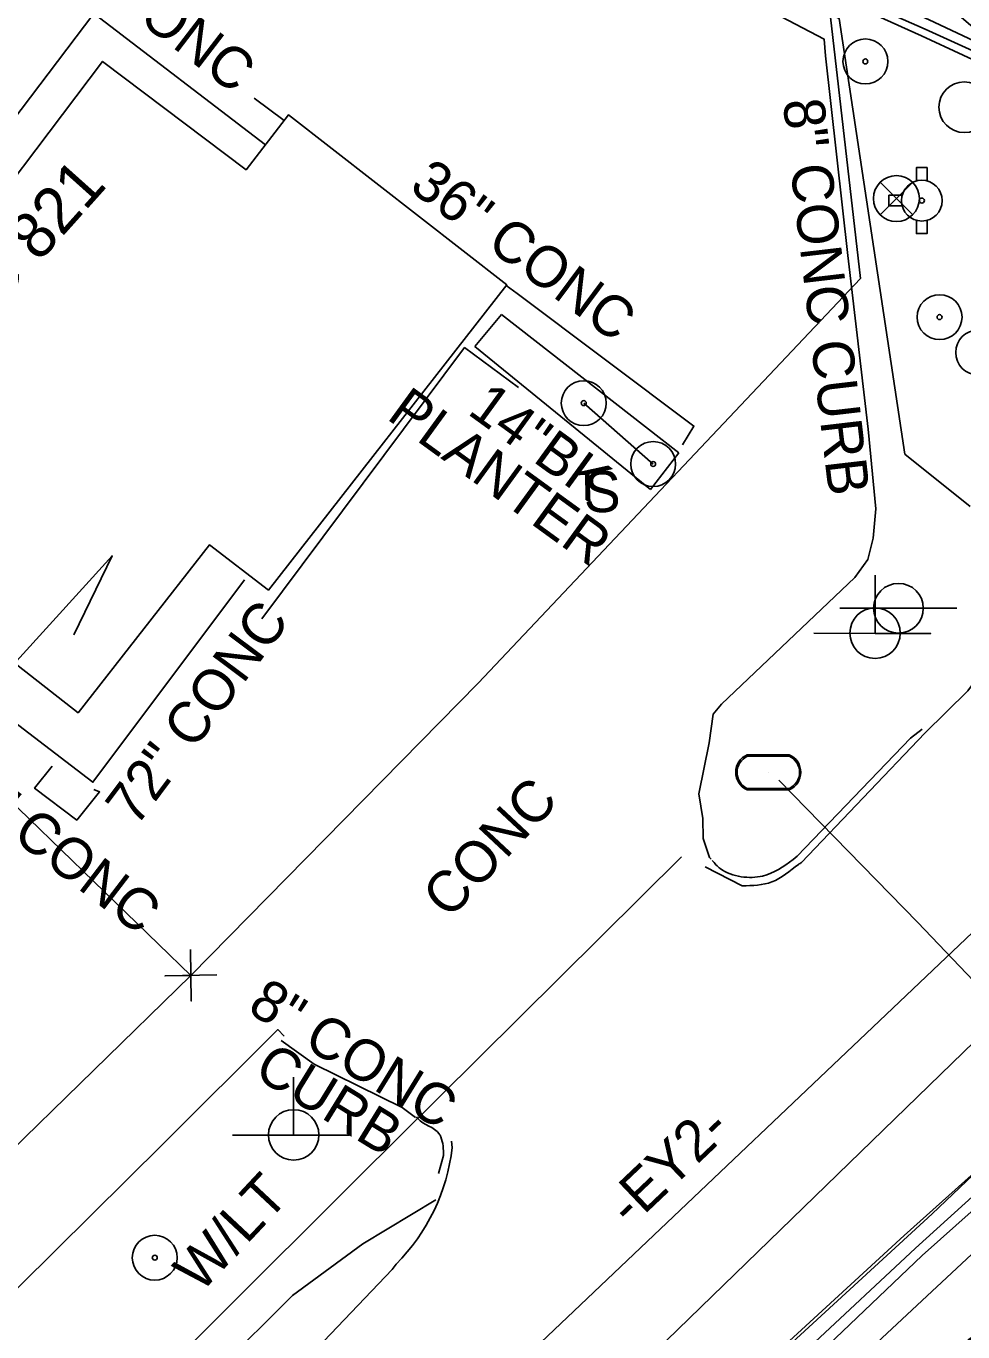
# Model space of a CAD drawing. Extents: x 2089016 to 2094354, y 862840 to 864725.
# Drawn here: x 2091453.6 to 2091544.5, y 863468.2 to 863595 of the extents above; entities that cross this region are included whole.
import ezdxf

# ---------------------------------------------------------------- set-up
doc = ezdxf.new("R2010")
doc.units = 0
for name, color, linetype in [('Exist Building', 7, 'Continuous'), ('Exist Building Text', 7, 'Continuous'), ('Exist Horizontal Alignment', 7, 'Continuous'), ('Exist Other Culture Sign Text', 7, 'Continuous'), ('Exist Property Corner CELL', 7, 'Continuous'), ('Exist Property Deed Book Text', 7, 'Continuous'), ('Exist Property Line', 7, 'Continuous'), ('Exist Property Same Owner Line CELL', 7, 'Continuous'), ('Exist Right of Way Line', 7, 'Continuous'), ('Exist Roads Curbs', 7, 'Continuous'), ('Exist Roads Curbs Text', 7, 'Continuous'), ('Exist Roads EOP', 7, 'Continuous'), ('Exist Roads EOP Other', 7, 'Continuous'), ('Exist Roads EOP Other Text', 7, 'Continuous'), ('Exist Roads EOT', 7, 'Continuous'), ('Exist Roads Soil', 7, 'Continuous'), ('Exist Structure Minor Pipes RCP 18 Inch Text', 7, 'Continuous'), ('Exist Utilities Other Unknown UG SUE LOS B', 7, 'Continuous'), ('Exist Utilities Power Joint Use Telephone Text', 7, 'Continuous'), ('Exist Utilities Telephone UG Cable SUE LOS B', 7, 'Continuous'), ('Exist Utilities Telephone UG FO SUE LOS B', 7, 'Continuous'), ('Exist Utilities Water UG Line SUE LOS B', 7, 'Continuous'), ('Exist Utilities Water UG Line SUE LOS C', 7, 'Continuous'), ('Pattern 1', 7, 'Continuous'), ('Prop Conc Driveway', 7, 'Continuous'), ('Prop Drainage Structure Junction Box Convert From Drop Inlet Label', 7, 'Continuous'), ('Prop Drainage Structure Pipe RCP 30in Class IV Label', 7, 'Continuous'), ('Prop Drainage Structure Pipe RCP 36in Class IV', 7, 'Continuous'), ('Prop Erosion Embankment Toe Protection with Rip Rap 2 Detail CELL', 7, 'Continuous'), ('Prop Erosion Rip Rap Pad at Outlet Label', 7, 'Continuous'), ('Prop SS Fill Line', 7, 'Continuous'), ('R5707_NCDOT_FS_170814 - Exist Property Same Owner Line CELL', 7, 'Continuous'), ('R5707_NCDOT_FS_170814 - Exist Roads EOT', 7, 'Continuous')]:
    doc.layers.add(name, color=color, linetype=linetype)

msp = doc.modelspace()

# ---------------------------------------------------------------- linework, layer by layer
at = {"layer": 'Exist Building'}
for p, q in [((2091497.12, 863563.86), (2091499.7, 863566.97)), ((2091499.7, 863566.97), (2091516.9, 863553.56)), ((2091514.15, 863549.99), (2091497.12, 863563.86)), ((2091516.9, 863553.56), (2091514.15, 863549.99))]:
    msp.add_line(p, q, dxfattribs=at)
msp.add_lwpolyline([(2091430.07, 863550.64), (2091460.98, 863591.55), (2091474.9, 863581.03), (2091479.03, 863586.37), (2091500.2, 863569.85), (2091477.08, 863540.22), (2091471.36, 863544.62), (2091458.6, 863528.31)], close=True, dxfattribs=at)
at = {"layer": 'Exist Horizontal Alignment'}
msp.add_line((2091563.2, 863523.9), (2091414.2, 863382.31), dxfattribs=at)
at = {"layer": 'Exist Property Corner CELL'}
msp.add_line((2091469.55, 863502.82), (2091469.55, 863502.82), dxfattribs=at)
msp.add_lwpolyline([(2091472.05, 863502.86), (2091467.05, 863502.77), (2091469.55, 863502.82), (2091469.59, 863500.32), (2091469.51, 863505.32)], dxfattribs=at)
at = {"layer": 'Exist Property Line'}
msp.add_line((2091397.62, 863572.38), (2091469.55, 863502.82), dxfattribs=at)
at = {"layer": 'Exist Property Same Owner Line CELL'}
msp.add_lwpolyline([(2091432.78, 863514.65), (2091428.25, 863506.53), (2091461.89, 863543.56), (2091458.17, 863535.87)], dxfattribs=at)
at = {"layer": 'Exist Right of Way Line'}
for p, q in [((2091531.4, 863597.96), (2091534.53, 863570.46)), ((2091534.53, 863570.46), (2091497.44, 863531.19)), ((2091497.44, 863531.19), (2091469.55, 863502.82)), ((2091469.55, 863502.82), (2091387.26, 863422.48))]:
    msp.add_line(p, q, dxfattribs=at)
at = {"layer": 'Exist Roads Curbs'}
msp.add_line((2091494.06, 863485.32), (2091493.58, 863483.58), dxfattribs=at)
for points in [[(2091506.04, 863606.89), (2091507.45, 863606.08), (2091531.01, 863593.71), (2091531.16, 863592.1), (2091533.32, 863572.69), (2091535.29, 863555.85), (2091536.04, 863548.12), (2091535.77, 863545.25), (2091535.25, 863543.2), (2091534, 863541.43), (2091521.05, 863529.14), (2091520.24, 863528.16), (2091519.85, 863525.4), (2091518.85, 863520.45), (2091519.25, 863518.04), (2091519.28, 863516.11), (2091519.9, 863514.25), (2091520.06, 863514.09)], [(2091476.78, 863583.45), (2091460.14, 863596.2), (2091444.26, 863575.3), (2091424.36, 863548.86), (2091460.04, 863521.56), (2091474.74, 863541.21)], [(2091478.6, 863585.81), (2091475.68, 863587.99)], [(2091517.26, 863554.31), (2091518.37, 863556.14), (2091501.22, 863569.01), (2091500.16, 863569.8)], [(2091476.43, 863537.44), (2091496.12, 863563.77), (2091501.36, 863559.9)], [(2091528.02, 863514.06), (2091528.41, 863514.38), (2091539.41, 863525.84), (2091540.53, 863526.71)], [(2091491.36, 863489.01), (2091490.07, 863489.98), (2091481.51, 863494.2), (2091478.31, 863496.51)]]:
    msp.add_lwpolyline(points, dxfattribs=at)
for points in [[(2091520.14, 863513.98), (2091520.93, 863513.18), (2091522.97, 863512.4), (2091525.04, 863512.46), (2091528.02, 863514.06)], [(2091491.46, 863489.07), (2091491.58, 863488.91), (2091493.65, 863487.44), (2091493.81, 863487.14), (2091494.06, 863485.32)]]:
    msp.add_spline(points, degree=3, dxfattribs=at)
at = {"layer": 'Exist Roads EOP'}
for p, q in [((2091523.07, 863511.51), (2091519.47, 863513.36)), ((2091494.84, 863486.71), (2091494.92, 863486.11))]:
    msp.add_line(p, q, dxfattribs=at)
for points in [[(2091614.68, 863551.59), (2091577.53, 863513.94), (2091541.5, 863479.68), (2091509.96, 863450.67), (2091494.8, 863436.99), (2091459.99, 863406.66), (2091416.33, 863367.37), (2091398.26, 863350.73), (2091360.43, 863313.58), (2091358.8, 863312), (2091365.83, 863304.95)], [(2091552.39, 863540.36), (2091544.96, 863530.43), (2091540.8, 863526.33), (2091528.82, 863513.78)], [(2091489.47, 863474.79), (2091489.08, 863474.28), (2091475.13, 863459.65)]]:
    msp.add_lwpolyline(points, dxfattribs=at)
msp.add_ellipse((2091476.13, 863488.15), major_axis=(11.89, 14.74), ratio=0.996637, start_param=4.605136, end_param=5.281022, dxfattribs=at)
for points in [[(2091506.95, 863615.21), (2091507.91, 863615.1), (2091509.2, 863615.04), (2091521.21, 863608.82), (2091540.28, 863598.73), (2091554.58, 863583.61), (2091560.58, 863560.92)], [(2091528.82, 863513.78), (2091528.53, 863513.58), (2091525.94, 863511.89), (2091523.07, 863511.51)]]:
    msp.add_spline(points, degree=3, dxfattribs=at)
at = {"layer": 'Exist Roads EOP Other'}
for points in [[(2091460.14, 863520.85), (2091460.69, 863520.62), (2091458.46, 863517.9), (2091454.37, 863520.98), (2091456.08, 863523.13)], [(2091449.43, 863469.21), (2091466.85, 863486.45), (2091478, 863497.55), (2091478.6, 863496.92)]]:
    msp.add_lwpolyline(points, dxfattribs=at)
at = {"layer": 'Exist Roads EOT'}
msp.add_lwpolyline([(2091706.36, 863652.5), (2091397.08, 863352.19), (2091355.5, 863316.61), (2091326.54, 863292.47), (2091281.78, 863256.45)], dxfattribs=at)
at = {"layer": 'Exist Roads Soil'}
msp.add_lwpolyline([(2091493.32, 863481.04), (2091486.24, 863476.74), (2091479.4, 863471.73), (2091472.27, 863464.61), (2091460.73, 863449.71), (2091440.99, 863428.83), (2091415.08, 863404.32), (2091394.34, 863385.45)], dxfattribs=at)
at = {"layer": 'Exist Utilities Other Unknown UG SUE LOS B'}
msp.add_lwpolyline([(2091172.82, 863219.12), (2091189.56, 863232.83), (2091223.7, 863259.95), (2091258.34, 863288.55), (2091306.54, 863326.84), (2091349.69, 863360.9), (2091383.97, 863388.39), (2091422.12, 863422.93), (2091458.41, 863455.88), (2091485.72, 863483.12), (2091517.18, 863514.31)], dxfattribs=at)
at = {"layer": 'Exist Utilities Telephone UG Cable SUE LOS B'}
for points in [[(2091454.96, 863634.5), (2091457.03, 863633.97), (2091467.15, 863628.47), (2091487.56, 863617.65), (2091505.48, 863610.21), (2091527.74, 863599.78), (2091540.47, 863594.03), (2091552.6, 863588.41), (2091572.7, 863579.22), (2091595.06, 863567.3), (2091603.68, 863560.49), (2091611.7, 863550.99), (2091613.1, 863548.2)], [(2091454.99, 863635.45), (2091457.34, 863634.62), (2091467.94, 863629.46), (2091488.57, 863620.26), (2091506.26, 863612.16), (2091528.56, 863601.4), (2091541.21, 863595.57), (2091553.17, 863589.94), (2091573.18, 863580.6), (2091596.59, 863570.44), (2091607.55, 863568.06), (2091618.49, 863563), (2091621.61, 863560.57), (2091622.37, 863558.05), (2091619.72, 863552.7)], [(2091455.06, 863634.88), (2091457.19, 863634.21), (2091467.51, 863628.96), (2091488.14, 863619.52), (2091505.67, 863611.33), (2091528.07, 863600.29), (2091540.83, 863594.66), (2091552.99, 863589.15), (2091573.13, 863579.97), (2091596.13, 863569.66), (2091606.07, 863565.77), (2091616.41, 863557.23), (2091619, 863554.32), (2091619.19, 863552.81)], [(2091247.57, 863225.28), (2091255.2, 863231.76), (2091270.68, 863245.65), (2091293.71, 863264.52), (2091333.53, 863296.81), (2091375.18, 863330.99), (2091410.87, 863360.54), (2091452.25, 863397.87), (2091497.36, 863439.5), (2091538.8, 863477.58), (2091575.02, 863510.02), (2091595.27, 863530.18), (2091614.5, 863546.3), (2091618.06, 863550.58)], [(2091248.62, 863178.37), (2091250.14, 863190.5), (2091251.53, 863208.74), (2091253.13, 863223.05), (2091256.17, 863230.53), (2091271.53, 863244.2), (2091294.74, 863263.1), (2091334.3, 863295.76), (2091377.39, 863329.19), (2091413.38, 863357.9), (2091454.91, 863395.52), (2091499.85, 863436.84), (2091540.52, 863475.63), (2091576.78, 863507.93), (2091596.62, 863528.68), (2091614.77, 863546.01), (2091618.54, 863550.22)]]:
    msp.add_lwpolyline(points, dxfattribs=at)
at = {"layer": 'Exist Utilities Telephone UG FO SUE LOS B'}
msp.add_lwpolyline([(2091245.15, 863178.44), (2091248.58, 863190.55), (2091250.66, 863208.87), (2091254.65, 863222.76), (2091257.81, 863229.5), (2091272.68, 863243.04), (2091295.46, 863262.53), (2091335.09, 863294.65), (2091334.98, 863294.7), (2091376.53, 863330.24), (2091412.12, 863359.29), (2091453.69, 863396.41), (2091499.25, 863437.79), (2091498.86, 863438.02), (2091539.9, 863476.32), (2091576.06, 863509.1), (2091597.41, 863527.51), (2091615.41, 863545.21), (2091619.02, 863549.76)], dxfattribs=at)
at = {"layer": 'Exist Utilities Water UG Line SUE LOS B'}
msp.add_lwpolyline([(2091526.61, 863521.76), (2091540.1, 863507.96), (2091556.33, 863490.95)], dxfattribs=at)
at = {"layer": 'Exist Utilities Water UG Line SUE LOS C'}
for points in [[(2091508.14, 863607.62), (2091532.47, 863595.72), (2091538.84, 863553.43), (2091545.2, 863548.34)], [(2091201.01, 863188.22), (2091260.06, 863228.02), (2091363.9, 863313.97), (2091438.95, 863378.82), (2091506.71, 863439.72), (2091582.98, 863510.86)]]:
    msp.add_lwpolyline(points, dxfattribs=at)
at = {"layer": 'Pattern 1'}
msp.add_line((2091525.6, 863522.53), (2091525.6, 863522.53), dxfattribs=at)
for points in [[(2091523.56, 863524.23), (2091527.64, 863524.23)], [(2091523.56, 863524.09), (2091527.64, 863524.09)], [(2091527.64, 863520.97), (2091523.54, 863520.97)], [(2091527.64, 863520.83), (2091523.54, 863520.83)]]:
    msp.add_lwpolyline(points, dxfattribs=at)
for centre, radius, start, end in [((2091524.29, 863522.53), 1.86, 113.178, 245.9794), ((2091524.3, 863522.52), 1.73, 115.3009, 243.7824), ((2091526.89, 863522.53), 1.86, 293.6483, 66.3084), ((2091526.9, 863522.53), 1.73, 295.1272, 64.8728)]:
    msp.add_arc(centre, radius, start, end, dxfattribs=at)
at = {"layer": 'Prop Conc Driveway'}
msp.add_line((2091507.68, 863558.37), (2091514.42, 863552.46), dxfattribs=at)
for centre, radius in [((2091507.68, 863558.37), 2.18), ((2091507.68, 863558.37), 0.24), ((2091514.42, 863552.46), 2.18), ((2091514.42, 863552.46), 0.24)]:
    msp.add_circle(centre, radius, dxfattribs=at)
at = {"layer": 'Prop Drainage Structure Junction Box Convert From Drop Inlet Label'}
for p, q in [((2091532.55, 863538.46), (2091543.89, 863538.46)), ((2091538.23, 863538.46), (2091538.23, 863538.46))]:
    msp.add_line(p, q, dxfattribs=at)
msp.add_circle((2091538.23, 863538.46), 2.41, dxfattribs=at)
at = {"layer": 'Prop Drainage Structure Pipe RCP 30in Class IV Label'}
msp.add_circle((2091544.62, 863587.1), 2.46, dxfattribs=at)
at = {"layer": 'Prop Drainage Structure Pipe RCP 36in Class IV'}
for centre, radius in [((2091535.02, 863591.54), 2.18), ((2091535.02, 863591.54), 0.24), ((2091542.22, 863566.72), 2.18), ((2091542.22, 863566.72), 0.24), ((2091545.97, 863563.29), 2.18), ((2091466.04, 863475.41), 2.18), ((2091466.04, 863475.41), 0.24)]:
    msp.add_circle(centre, radius, dxfattribs=at)
at = {"layer": 'Prop Erosion Embankment Toe Protection with Rip Rap 2 Detail CELL'}
msp.add_lwpolyline([(2091539.61, 863579.81), (2091536.46, 863576.66), (2091538.03, 863578.23), (2091539.61, 863576.66), (2091536.46, 863579.81)], dxfattribs=at)
msp.add_circle((2091538.03, 863578.23), 2.23, dxfattribs=at)
at = {"layer": 'Prop Erosion Rip Rap Pad at Outlet Label'}
msp.add_line((2091540.5, 863578.03), (2091540.5, 863578.03), dxfattribs=at)
for points in [[(2091539.98, 863579.95), (2091539.98, 863581.23), (2091541.01, 863581.23), (2091541.01, 863579.92)], [(2091538.58, 863578.55), (2091537.3, 863578.55), (2091537.3, 863577.52), (2091538.58, 863577.52)], [(2091539.98, 863576.12), (2091539.98, 863574.83), (2091541.01, 863574.83), (2091541.01, 863576.15)]]:
    msp.add_lwpolyline(points, dxfattribs=at)
for radius in [1.98, 0.243]:
    msp.add_circle((2091540.5, 863578.03), radius, dxfattribs=at)
at = {"layer": 'Prop SS Fill Line'}
for p, q in [((2091535.96, 863536.03), (2091535.96, 863536.03)), ((2091479.52, 863487.32), (2091479.52, 863487.32))]:
    msp.add_line(p, q, dxfattribs=at)
for points in [[(2091530.02, 863536.03), (2091541.36, 863536), (2091535.96, 863536.01), (2091535.96, 863541.66)], [(2091473.58, 863487.32), (2091484.92, 863487.29), (2091479.52, 863487.3), (2091479.52, 863492.95)]]:
    msp.add_lwpolyline(points, dxfattribs=at)
for centre in [(2091535.96, 863536.04), (2091479.52, 863487.33)]:
    msp.add_circle(centre, 2.45, dxfattribs=at)
at = {"layer": 'R5707_NCDOT_FS_170814 - Exist Property Same Owner Line CELL'}
msp.add_lwpolyline([(2091432.78, 863514.65), (2091428.25, 863506.53), (2091461.89, 863543.56), (2091458.17, 863535.87)], dxfattribs=at)
at = {"layer": 'R5707_NCDOT_FS_170814 - Exist Roads EOT'}
msp.add_lwpolyline([(2091706.36, 863652.5), (2091397.08, 863352.19), (2091355.5, 863316.61), (2091326.54, 863292.47), (2091281.78, 863256.45)], dxfattribs=at)

# ---------------------------------------------------------------- texts
at = {"layer": 'Exist Building Text'}
for s, p in [('PLANTER', (2091488.44, 863556.9)), ('14"BK', (2091496.28, 863557.39))]:
    msp.add_text(s, height=4, rotation=323.9899, dxfattribs=at).set_placement(p)
at = {"layer": 'Exist Horizontal Alignment'}
msp.add_text('-EY2-', height=4, rotation=43.5384, dxfattribs=at).set_placement((2091512.22, 863478.28))
at = {"layer": 'Exist Other Culture Sign Text'}
msp.add_text('S', height=4, dxfattribs=at).set_placement((2091507.7, 863547.79))
at = {"layer": 'Exist Property Deed Book Text'}
msp.add_text('DB 688 PG 821', height=4.5, rotation=48.1706, dxfattribs=at).set_placement((2091433.38, 863548.04))
at = {"layer": 'Exist Roads Curbs Text'}
for s, rotation, p in [('48" CONC', 322.5428, (2091453.84, 863603.55)), ('8" CONC CURB', 276.6757, (2091526.99, 863587.73)), ('36" CONC', 323.3881, (2091490.61, 863579.12)), ('72" CONC', 53.2249, (2091464.22, 863517.12)), ('60" CONC', 322.5805, (2091444.65, 863521.86)), ('8" CONC ', 328.3996, (2091474.89, 863499.33)), ('CURB', 328.3996, (2091475.49, 863493.08))]:
    msp.add_text(s, height=4, rotation=rotation, dxfattribs=at).set_placement(p)
at = {"layer": 'Exist Roads EOP Other Text'}
msp.add_text(' CONC', height=4, rotation=46.9126, dxfattribs=at).set_placement((2091493.61, 863507.08))
at = {"layer": 'Exist Structure Minor Pipes RCP 18 Inch Text'}
msp.add_text('18" RCP', height=4, rotation=44.9223, dxfattribs=at).set_placement((2091539.53, 863456.43))
at = {"layer": 'Exist Utilities Power Joint Use Telephone Text'}
msp.add_text('W/LT', height=4, rotation=46.8629, dxfattribs=at).set_placement((2091470.48, 863471.87))

doc.saveas('drawing.dxf')
